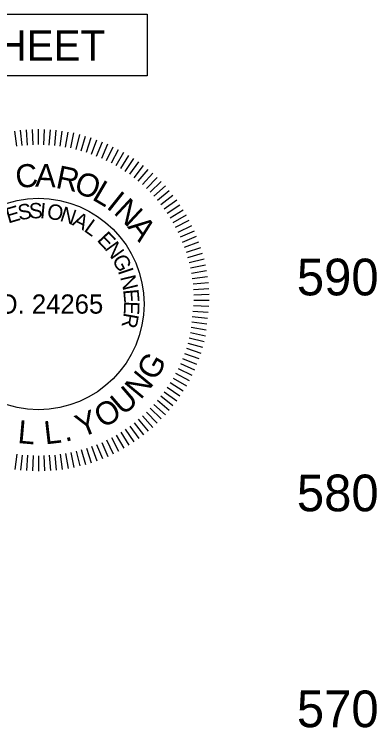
# Model space of a CAD drawing. Extents: x 1964377 to 1966966, y 1116414 to 1123213.
# Drawn here: x 1966865.8 to 1966949.9, y 1119076.7 to 1119241.9 of the extents above; entities that cross this region are included whole.
import ezdxf

# ---------------------------------------------------------------- set-up
doc = ezdxf.new("R2010")
doc.units = 0
for name, color, linetype in [('RD_DDB_Profile_Elev', 7, 'Continuous'), ('RD_Sketch1', 7, 'Continuous'), ('RD_TX_PEShield', 7, 'Continuous')]:
    doc.layers.add(name, color=color, linetype=linetype)

msp = doc.modelspace()

# ---------------------------------------------------------------- linework, layer by layer
at = {"layer": 'RD_Sketch1'}
msp.add_lwpolyline([(1966596.19, 1119241.9), (1966896.61, 1119241.9), (1966896.61, 1119227.64), (1966596.19, 1119227.64)], close=True, dxfattribs=at)
at = {"layer": 'RD_TX_PEShield'}
for p, q in [((1966866.44, 1119211.33), (1966865.94, 1119214.85)), ((1966866.44, 1119211.33), (1966865.94, 1119214.85)), ((1966867.68, 1119211.52), (1966867.31, 1119215.06)), ((1966867.68, 1119211.52), (1966867.31, 1119215.06)), ((1966868.94, 1119211.59), (1966868.69, 1119215.14)), ((1966868.94, 1119211.59), (1966868.69, 1119215.14)), ((1966870.19, 1119211.65), (1966870.07, 1119215.21)), ((1966870.19, 1119211.65), (1966870.07, 1119215.21)), ((1966871.45, 1119211.72), (1966871.45, 1119215.28)), ((1966871.45, 1119211.72), (1966871.45, 1119215.28)), ((1966872.7, 1119211.65), (1966872.83, 1119215.21)), ((1966872.7, 1119211.65), (1966872.83, 1119215.21)), ((1966873.96, 1119211.59), (1966874.21, 1119215.14)), ((1966873.96, 1119211.59), (1966874.21, 1119215.14)), ((1966875.21, 1119211.52), (1966875.59, 1119215.06)), ((1966875.21, 1119211.52), (1966875.59, 1119215.06)), ((1966876.46, 1119211.33), (1966876.95, 1119214.85)), ((1966876.46, 1119211.33), (1966876.95, 1119214.85)), ((1966877.7, 1119211.13), (1966878.32, 1119214.63)), ((1966877.7, 1119211.13), (1966878.32, 1119214.63)), ((1966878.94, 1119210.93), (1966879.68, 1119214.41)), ((1966878.94, 1119210.93), (1966879.68, 1119214.41)), ((1966878.94, 1119210.93), (1966879.68, 1119214.41)), ((1966880.16, 1119210.61), (1966881.02, 1119214.06)), ((1966880.16, 1119210.61), (1966881.02, 1119214.06)), ((1966880.16, 1119210.61), (1966881.02, 1119214.06)), ((1966881.37, 1119210.28), (1966882.35, 1119213.7)), ((1966881.37, 1119210.28), (1966882.35, 1119213.7)), ((1966881.37, 1119210.28), (1966882.35, 1119213.7)), ((1966882.59, 1119209.96), (1966883.69, 1119213.34)), ((1966882.59, 1119209.96), (1966883.69, 1119213.34)), ((1966882.59, 1119209.96), (1966883.69, 1119213.34)), ((1966883.76, 1119209.51), (1966884.98, 1119212.85)), ((1966883.76, 1119209.51), (1966884.98, 1119212.85)), ((1966883.76, 1119209.51), (1966884.98, 1119212.85)), ((1966884.93, 1119209.06), (1966886.26, 1119212.35)), ((1966884.93, 1119209.06), (1966886.26, 1119212.35)), ((1966884.93, 1119209.06), (1966886.26, 1119212.35)), ((1966886.11, 1119208.6), (1966887.56, 1119211.86)), ((1966886.11, 1119208.6), (1966887.56, 1119211.86)), ((1966886.11, 1119208.6), (1966887.56, 1119211.86)), ((1966887.23, 1119208.03), (1966888.79, 1119211.23)), ((1966887.23, 1119208.03), (1966888.79, 1119211.23)), ((1966887.23, 1119208.03), (1966888.79, 1119211.23)), ((1966888.35, 1119207.46), (1966890.02, 1119210.6)), ((1966888.35, 1119207.46), (1966890.02, 1119210.6)), ((1966888.35, 1119207.46), (1966890.02, 1119210.6)), ((1966889.47, 1119206.89), (1966891.25, 1119209.97)), ((1966889.47, 1119206.89), (1966891.25, 1119209.97)), ((1966889.47, 1119206.89), (1966891.25, 1119209.97)), ((1966890.52, 1119206.21), (1966892.41, 1119209.22)), ((1966890.52, 1119206.21), (1966892.41, 1119209.22)), ((1966890.52, 1119206.21), (1966892.41, 1119209.22)), ((1966891.58, 1119205.52), (1966893.57, 1119208.47)), ((1966891.58, 1119205.52), (1966893.57, 1119208.47)), ((1966891.58, 1119205.52), (1966893.57, 1119208.47)), ((1966892.63, 1119204.84), (1966894.73, 1119207.72)), ((1966892.63, 1119204.84), (1966894.73, 1119207.72)), ((1966892.63, 1119204.84), (1966894.73, 1119207.72)), ((1966893.61, 1119204.04), (1966895.8, 1119206.85)), ((1966893.61, 1119204.04), (1966895.8, 1119206.85)), ((1966893.61, 1119204.04), (1966895.8, 1119206.85)), ((1966894.59, 1119203.25), (1966896.87, 1119205.98)), ((1966894.59, 1119203.25), (1966896.87, 1119205.98)), ((1966894.59, 1119203.25), (1966896.87, 1119205.98)), ((1966895.57, 1119202.46), (1966897.95, 1119205.11)), ((1966895.57, 1119202.46), (1966897.95, 1119205.11)), ((1966895.57, 1119202.46), (1966897.95, 1119205.11)), ((1966896.46, 1119201.57), (1966898.93, 1119204.13)), ((1966896.46, 1119201.57), (1966898.93, 1119204.13)), ((1966896.46, 1119201.57), (1966898.93, 1119204.13)), ((1966897.34, 1119200.68), (1966899.9, 1119203.15)), ((1966897.34, 1119200.68), (1966899.9, 1119203.15)), ((1966897.34, 1119200.68), (1966899.9, 1119203.15)), ((1966898.23, 1119199.79), (1966900.88, 1119202.18)), ((1966898.23, 1119199.79), (1966900.88, 1119202.18)), ((1966898.23, 1119199.79), (1966900.88, 1119202.18)), ((1966899.03, 1119198.82), (1966901.75, 1119201.1)), ((1966899.03, 1119198.82), (1966901.75, 1119201.1)), ((1966899.03, 1119198.82), (1966901.75, 1119201.1)), ((1966899.82, 1119197.84), (1966902.62, 1119200.03)), ((1966899.82, 1119197.84), (1966902.62, 1119200.03)), ((1966899.82, 1119197.84), (1966902.62, 1119200.03)), ((1966900.61, 1119196.86), (1966903.49, 1119198.95)), ((1966900.61, 1119196.86), (1966903.49, 1119198.95)), ((1966900.61, 1119196.86), (1966903.49, 1119198.95)), ((1966901.29, 1119195.81), (1966904.24, 1119197.8)), ((1966901.29, 1119195.81), (1966904.24, 1119197.8)), ((1966901.29, 1119195.81), (1966904.24, 1119197.8)), ((1966901.98, 1119194.75), (1966904.99, 1119196.64)), ((1966901.98, 1119194.75), (1966904.99, 1119196.64)), ((1966901.98, 1119194.75), (1966904.99, 1119196.64)), ((1966902.66, 1119193.7), (1966905.75, 1119195.48)), ((1966902.66, 1119193.7), (1966905.75, 1119195.48)), ((1966902.66, 1119193.7), (1966905.75, 1119195.48)), ((1966903.23, 1119192.58), (1966906.37, 1119194.25)), ((1966903.23, 1119192.58), (1966906.37, 1119194.25)), ((1966903.23, 1119192.58), (1966906.37, 1119194.25)), ((1966903.8, 1119191.46), (1966907, 1119193.02)), ((1966903.8, 1119191.46), (1966907, 1119193.02)), ((1966903.8, 1119191.46), (1966907, 1119193.02)), ((1966904.38, 1119190.34), (1966907.63, 1119191.78)), ((1966904.38, 1119190.34), (1966907.63, 1119191.78)), ((1966904.38, 1119190.34), (1966907.63, 1119191.78)), ((1966904.83, 1119189.16), (1966908.12, 1119190.49)), ((1966904.83, 1119189.16), (1966908.12, 1119190.49)), ((1966904.83, 1119189.16), (1966908.12, 1119190.49)), ((1966905.28, 1119187.99), (1966908.62, 1119189.2)), ((1966905.28, 1119187.99), (1966908.62, 1119189.2)), ((1966905.28, 1119187.99), (1966908.62, 1119189.2)), ((1966905.73, 1119186.81), (1966909.11, 1119187.91)), ((1966905.73, 1119186.81), (1966909.11, 1119187.91)), ((1966905.73, 1119186.81), (1966909.11, 1119187.91)), ((1966906.05, 1119185.6), (1966909.47, 1119186.58)), ((1966906.05, 1119185.6), (1966909.47, 1119186.58)), ((1966906.05, 1119185.6), (1966909.47, 1119186.58)), ((1966906.38, 1119184.38), (1966909.83, 1119185.25)), ((1966906.38, 1119184.38), (1966909.83, 1119185.25)), ((1966906.38, 1119184.38), (1966909.83, 1119185.25)), ((1966906.7, 1119183.17), (1966910.19, 1119183.91)), ((1966906.7, 1119183.17), (1966910.19, 1119183.91)), ((1966906.7, 1119183.17), (1966910.19, 1119183.91)), ((1966906.9, 1119181.93), (1966910.4, 1119182.54)), ((1966906.9, 1119181.93), (1966910.4, 1119182.54)), ((1966906.9, 1119181.93), (1966910.4, 1119182.54)), ((1966907.1, 1119180.69), (1966910.62, 1119181.18)), ((1966907.1, 1119180.69), (1966910.62, 1119181.18)), ((1966907.1, 1119180.69), (1966910.62, 1119181.18)), ((1966907.29, 1119179.44), (1966910.83, 1119179.82)), ((1966907.29, 1119179.44), (1966910.83, 1119179.82)), ((1966907.29, 1119179.44), (1966910.83, 1119179.82)), ((1966907.36, 1119178.19), (1966910.91, 1119178.43)), ((1966907.36, 1119178.19), (1966910.91, 1119178.43)), ((1966907.36, 1119178.19), (1966910.91, 1119178.43)), ((1966907.43, 1119176.93), (1966910.98, 1119177.06)), ((1966907.43, 1119176.93), (1966910.98, 1119177.06)), ((1966907.43, 1119176.93), (1966910.98, 1119177.06)), ((1966907.36, 1119174.42), (1966910.91, 1119174.3)), ((1966907.36, 1119174.42), (1966910.91, 1119174.3)), ((1966907.49, 1119175.68), (1966911.05, 1119175.68)), ((1966907.49, 1119175.68), (1966911.05, 1119175.68)), ((1966907.49, 1119175.68), (1966911.05, 1119175.68)), ((1966907.23, 1119173.17), (1966910.76, 1119172.93)), ((1966907.23, 1119173.17), (1966910.76, 1119172.93)), ((1966907.1, 1119171.93), (1966910.62, 1119171.56)), ((1966907.1, 1119171.93), (1966910.62, 1119171.56)), ((1966906.84, 1119169.44), (1966910.33, 1119168.82)), ((1966906.84, 1119169.44), (1966910.33, 1119168.82)), ((1966906.97, 1119170.68), (1966910.48, 1119170.19)), ((1966906.97, 1119170.68), (1966910.48, 1119170.19)), ((1966906.7, 1119168.18), (1966910.19, 1119167.44)), ((1966906.7, 1119168.18), (1966910.19, 1119167.44)), ((1966906.38, 1119166.97), (1966909.83, 1119166.11)), ((1966906.38, 1119166.97), (1966909.83, 1119166.11)), ((1966905.73, 1119164.54), (1966909.11, 1119163.44)), ((1966905.73, 1119164.54), (1966909.11, 1119163.44)), ((1966906.05, 1119165.75), (1966909.47, 1119164.77)), ((1966906.05, 1119165.75), (1966909.47, 1119164.77)), ((1966905.28, 1119163.36), (1966908.62, 1119162.15)), ((1966905.28, 1119163.36), (1966908.62, 1119162.15)), ((1966904.83, 1119162.19), (1966908.12, 1119160.86)), ((1966904.83, 1119162.19), (1966908.12, 1119160.86)), ((1966903.8, 1119159.89), (1966907, 1119158.33)), ((1966903.8, 1119159.89), (1966907, 1119158.33)), ((1966904.38, 1119161.01), (1966907.63, 1119159.57)), ((1966904.38, 1119161.01), (1966907.63, 1119159.57)), ((1966903.23, 1119158.77), (1966906.37, 1119157.1)), ((1966903.23, 1119158.77), (1966906.37, 1119157.1)), ((1966901.98, 1119156.6), (1966904.99, 1119154.71)), ((1966901.98, 1119156.6), (1966904.99, 1119154.71)), ((1966902.66, 1119157.65), (1966905.75, 1119155.87)), ((1966902.66, 1119157.65), (1966905.75, 1119155.87)), ((1966900.61, 1119154.49), (1966903.49, 1119152.4)), ((1966900.61, 1119154.49), (1966903.49, 1119152.4)), ((1966901.29, 1119155.54), (1966904.24, 1119153.56)), ((1966901.29, 1119155.54), (1966904.24, 1119153.56)), ((1966899.82, 1119153.51), (1966902.62, 1119151.32)), ((1966899.82, 1119153.51), (1966902.62, 1119151.32)), ((1966898.23, 1119151.56), (1966900.88, 1119149.17)), ((1966898.23, 1119151.56), (1966900.88, 1119149.17)), ((1966899.03, 1119152.53), (1966901.75, 1119150.25)), ((1966899.03, 1119152.53), (1966901.75, 1119150.25)), ((1966896.46, 1119149.78), (1966898.93, 1119147.22)), ((1966896.46, 1119149.78), (1966898.93, 1119147.22)), ((1966897.34, 1119150.67), (1966899.9, 1119148.2)), ((1966897.34, 1119150.67), (1966899.9, 1119148.2)), ((1966894.59, 1119148.1), (1966896.87, 1119145.37)), ((1966894.59, 1119148.1), (1966896.87, 1119145.37)), ((1966895.57, 1119148.89), (1966897.95, 1119146.24)), ((1966892.63, 1119146.51), (1966894.73, 1119143.63)), ((1966892.63, 1119146.51), (1966894.73, 1119143.63)), ((1966893.61, 1119147.31), (1966895.8, 1119144.5)), ((1966893.61, 1119147.31), (1966895.8, 1119144.5)), ((1966890.52, 1119145.14), (1966892.41, 1119142.13)), ((1966890.52, 1119145.14), (1966892.41, 1119142.13)), ((1966891.58, 1119145.83), (1966893.57, 1119142.88)), ((1966891.58, 1119145.83), (1966893.57, 1119142.88)), ((1966887.23, 1119143.32), (1966888.79, 1119140.12)), ((1966887.23, 1119143.32), (1966888.79, 1119140.12)), ((1966888.35, 1119143.89), (1966890.02, 1119140.75)), ((1966888.35, 1119143.89), (1966890.02, 1119140.75)), ((1966889.47, 1119144.46), (1966891.25, 1119141.38)), ((1966889.47, 1119144.46), (1966891.25, 1119141.38)), ((1966882.59, 1119141.39), (1966883.69, 1119138.01)), ((1966882.59, 1119141.39), (1966883.69, 1119138.01)), ((1966883.76, 1119141.85), (1966884.98, 1119138.5)), ((1966883.76, 1119141.85), (1966884.98, 1119138.5)), ((1966884.93, 1119142.3), (1966886.26, 1119139)), ((1966884.93, 1119142.3), (1966886.26, 1119139)), ((1966886.11, 1119142.75), (1966887.56, 1119139.49)), ((1966886.11, 1119142.75), (1966887.56, 1119139.49)), ((1966866.44, 1119140.02), (1966865.94, 1119136.5)), ((1966866.44, 1119140.02), (1966865.94, 1119136.5)), ((1966867.68, 1119139.83), (1966867.31, 1119136.29)), ((1966867.68, 1119139.83), (1966867.31, 1119136.29)), ((1966868.94, 1119139.76), (1966868.69, 1119136.22)), ((1966868.94, 1119139.76), (1966868.69, 1119136.22)), ((1966870.19, 1119139.7), (1966870.07, 1119136.14)), ((1966870.19, 1119139.7), (1966870.07, 1119136.14)), ((1966871.45, 1119139.63), (1966871.45, 1119136.07)), ((1966871.45, 1119139.63), (1966871.45, 1119136.07)), ((1966872.7, 1119139.7), (1966872.83, 1119136.14)), ((1966872.7, 1119139.7), (1966872.83, 1119136.14)), ((1966873.96, 1119139.76), (1966874.21, 1119136.22)), ((1966873.96, 1119139.76), (1966874.21, 1119136.22)), ((1966875.21, 1119139.83), (1966875.59, 1119136.29)), ((1966875.21, 1119139.83), (1966875.59, 1119136.29)), ((1966876.46, 1119140.02), (1966876.95, 1119136.5)), ((1966876.46, 1119140.02), (1966876.95, 1119136.5)), ((1966877.7, 1119140.22), (1966878.32, 1119136.72)), ((1966877.7, 1119140.22), (1966878.32, 1119136.72)), ((1966878.94, 1119140.42), (1966879.68, 1119136.94)), ((1966878.94, 1119140.42), (1966879.68, 1119136.94)), ((1966880.16, 1119140.74), (1966881.02, 1119137.29)), ((1966880.16, 1119140.74), (1966881.02, 1119137.29)), ((1966881.37, 1119141.07), (1966882.35, 1119137.65)), ((1966881.37, 1119141.07), (1966882.35, 1119137.65))]:
    msp.add_line(p, q, dxfattribs=at)
msp.add_circle((1966871.45, 1119174.8), 24.48, dxfattribs=at)

# ---------------------------------------------------------------- texts
at = {"layer": 'RD_DDB_Profile_Elev'}
for s, p in [('590', (1966931.34, 1119176.8)), ('580', (1966931.34, 1119126.8)), ('570', (1966931.34, 1119076.8))]:
    msp.add_text(s, height=8.5, dxfattribs=at).set_placement(p)
at = {"layer": 'RD_Sketch1'}
msp.add_text('ALIGNMENT CONTROL CAN BE FOUND ON REFERENCE SHEET', height=7, dxfattribs=at).set_placement((1966599.83, 1119231.18))
at = {"layer": 'RD_TX_PEShield'}
for s, height, rotation, p in [('C', 5.34, 6.8832, (1966866.44, 1119201.54)), ('A', 5.34, 357.9448, (1966870.66, 1119201.99)), ('R', 5.34, 348.267, (1966875.24, 1119201.73)), ('O', 5.34, 339.3286, (1966879.38, 1119200.82)), ('L', 5.34, 329.6507, (1966883.64, 1119199.11)), ('I', 5.34, 321.4663, (1966886.98, 1119197.13)), ('N', 5.34, 317.0007, (1966888.67, 1119195.85)), ('E', 3.56, 16.1843, (1966864.44, 1119193.43)), ('S', 3.56, 8.6909, (1966866.93, 1119194.19)), ('S', 3.56, 1.79, (1966869.3, 1119194.59)), ('I', 3.56, 354.889, (1966871.69, 1119194.7)), ('O', 3.56, 350.4045, (1966873.25, 1119194.62)), ('N', 3.56, 341.7029, (1966876.22, 1119194.12)), ('A', 3.56, 333.0013, (1966879.09, 1119193.18)), ('L', 3.56, 324.2997, (1966881.79, 1119191.81)), ('A', 5.34, 307.3229, (1966891.96, 1119192.66)), ('E', 3.56, 313.2251, (1966884.86, 1119189.51)), ('N', 3.56, 305.7317, (1966886.66, 1119187.63)), ('G', 3.56, 297.0301, (1966888.43, 1119185.18)), ('I', 3.56, 288.3285, (1966889.81, 1119182.49)), ('N', 3.56, 283.8441, (1966890.35, 1119181.03)), ('E', 3.56, 275.1424, (1966891.08, 1119178.1)), ('E', 3.56, 267.6491, (1966891.34, 1119175.51)), ('R', 3.56, 260.1557, (1966891.26, 1119172.91)), ('G', 5.34, 60.1113, (1966898.56, 1119156.77)), ('N', 5.34, 50.4335, (1966895.14, 1119152.47)), ('U', 5.34, 40.7556, (1966891.05, 1119148.81)), ('O', 5.34, 31.0778, (1966886.4, 1119145.88)), ('Y', 5.34, 21.4, (1966881.33, 1119143.78)), ('L', 5.34, 354.9835, (1966866.5, 1119142.62)), ('L', 5.34, 6.5171, (1966873.03, 1119142.28)), ('.', 5.34, 14.7016, (1966877.64, 1119142.84))]:
    msp.add_text(s, height=height, rotation=rotation, dxfattribs=at).set_placement(p)
msp.add_text('NO. 24265', height=4.45, dxfattribs=at).set_placement((1966857.69, 1119172.57))

doc.saveas('drawing.dxf')
